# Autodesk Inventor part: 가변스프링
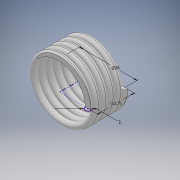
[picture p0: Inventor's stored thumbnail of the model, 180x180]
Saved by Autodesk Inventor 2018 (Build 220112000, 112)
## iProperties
Created: 2020-06
Part Number: 가변스프링
Material: 일반
Document SubType Name: Modeling
Designer: USER
Density: 1 g/cm^3
Appearance: 기본값
Mass: 0.954034 g
Surface Area: 19.5659 cm^2
Volume: 0.954034 cm^3
Author: USER
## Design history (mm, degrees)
sketch "스케치1"
  geometry: L1 (0, 0)-(10, 0); L2 (10, 0)-(10, 12.7); L3 (10, 12.7)-(0, 12.7); L4 (0, 12.7)-(0, 0); C1 r 1 at (10, 0)
  constraints: 8 end point, 2 parallel, 1 centre point, 1 coincident, 1 horizontal, 1 perpendicular
  dimensions: "d1" = 12.7 distance of L2.end L1.end (derived); "d2" = 2 diameter of C1; "d15" = 20 diameter of L2 L4
feature "코일1" sketch "스케치1" pitch "d3" = 10; turns "d5" = 5; dims "d4" = 12.7 (= d1), "d6" = 0, angle "d7" = 90 deg, angle "d8" = 90 deg, "d9" = 0, "d10" = 0
sketch "스케치2"
  geometry: L1 (-9, 0)-(-11, 0) reference; 1 further point
  constraints: 1 horizontal alignment
extrude "돌출1" cut sketch "스케치2" extent not by distance; stored distance "d11" = 10; taper "d12" = 0 deg
node "작업 평면1"
sketch "스케치3"
  geometry: L1 (9, 0)-(11, 0) reference; 2 further points
  constraints: 1 other
extrude "돌출2" cut sketch "스케치3" extent not by distance; stored distance "d13" = 10; taper "d14" = 0 deg
node "솔리드1"
node "절단 모서리 투영1"
node "절단 모서리 투영2"
